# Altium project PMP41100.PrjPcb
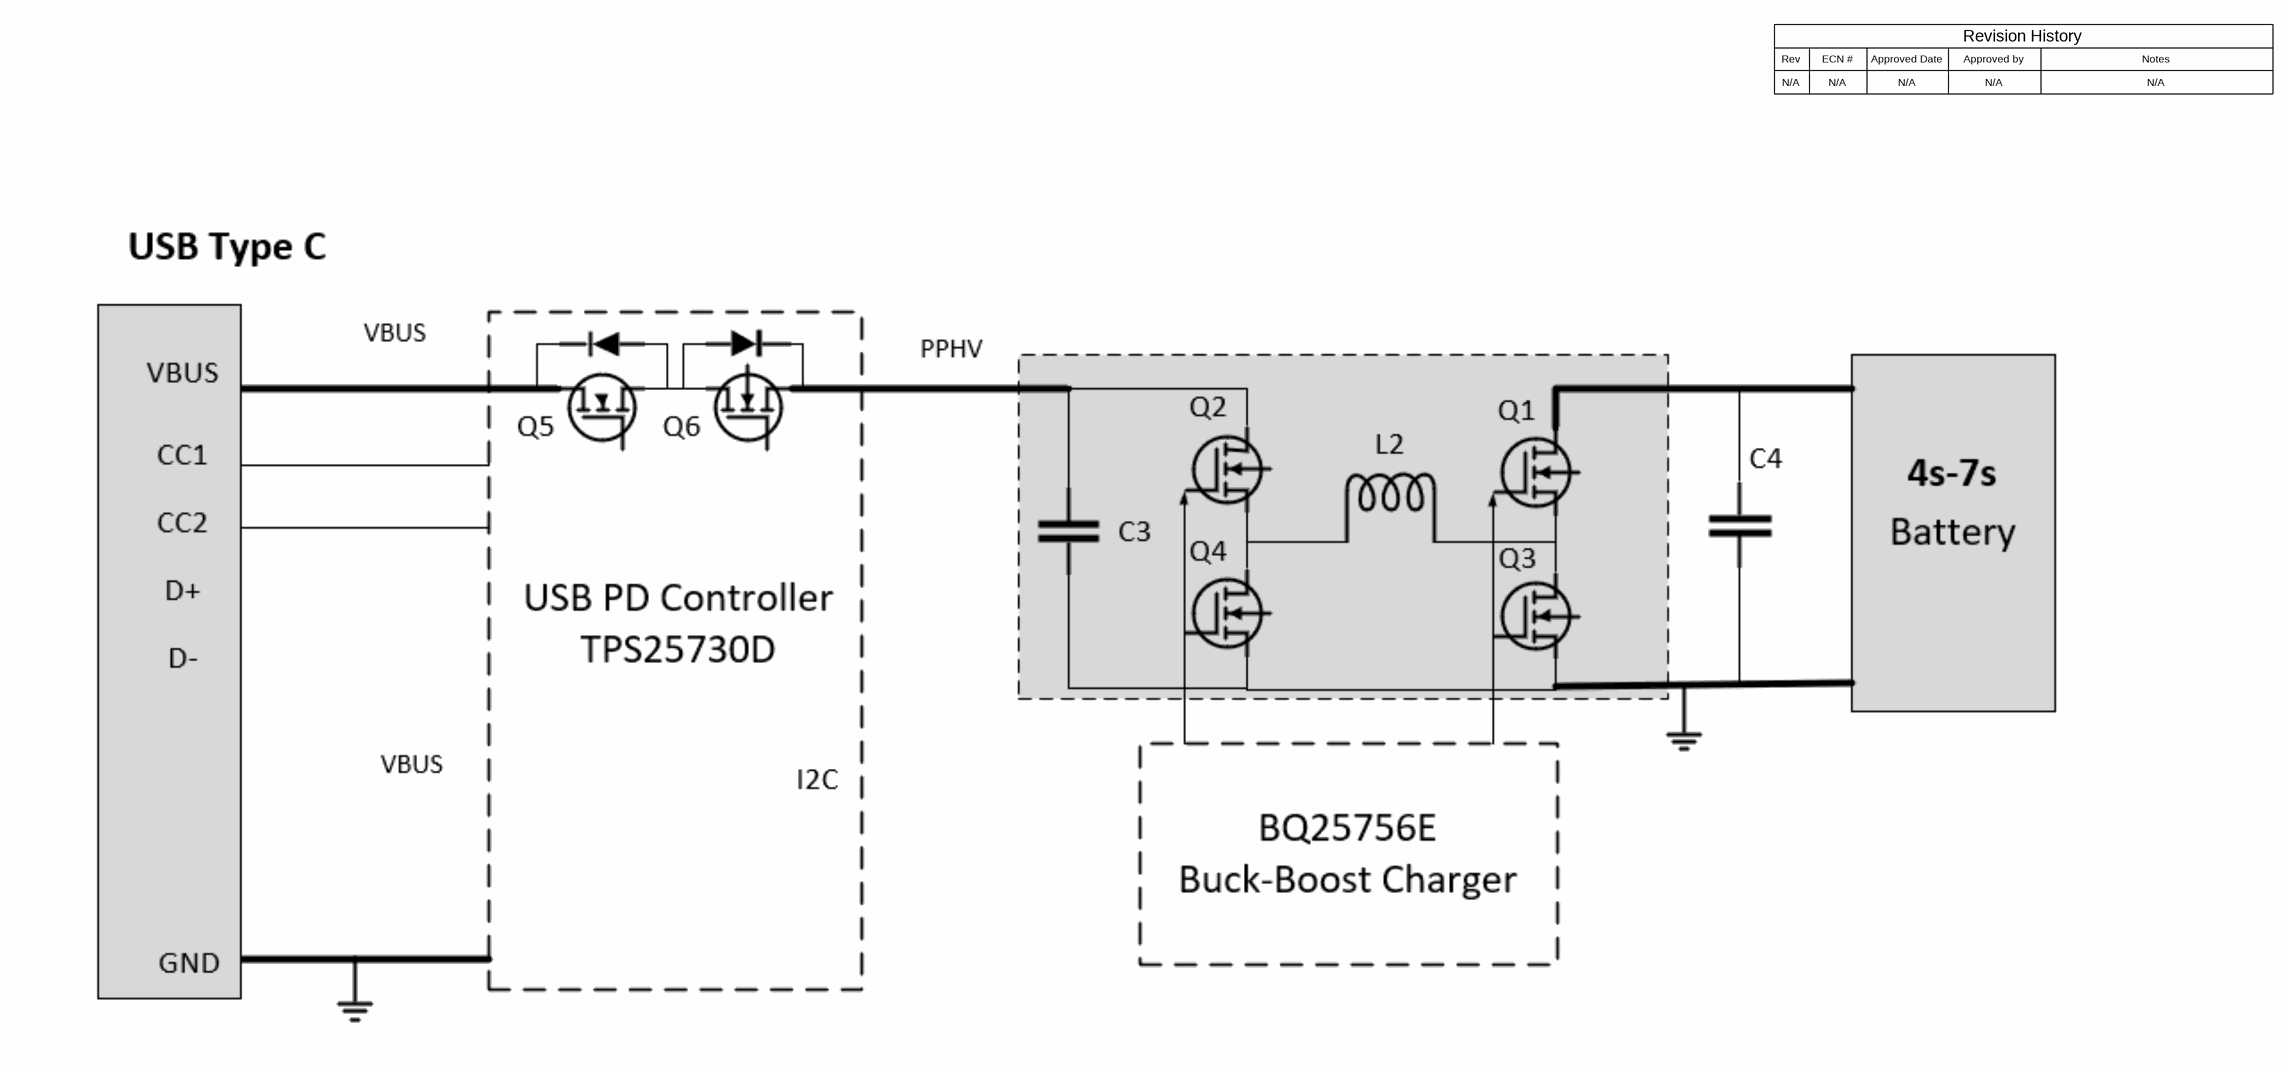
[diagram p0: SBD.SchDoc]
TechSupport: http://www.ti.com/support; SCH_Rev: E1; PRJ_Title: PMP41100; PRJ_Number: PMP41100; PRJ_Engineer: Max Wang; PRJ_Customer: Public Release; PCB_Rev: E1; PCB_Layout: Max Wang; CopyrightYear: 2018
4 sheets, 102 parts. Net scope: flat (ports and power ports of the same name join across sheets).
Board file: PMP41100.PcbDoc
Sheets:
  SBD.SchDoc
  PD Controller.SchDoc
  Charger BQ25756.SchDoc
  Hardware.SchDoc

## Sheet SBD.SchDoc
size A2; Date: Not shown in title block; ApprovedBy: Not shown in title block; CheckedBy: Not shown in title block; Author: Not shown in title block; CompanyName: Not shown in title block; Engineer: Not shown in title block; Organization: Not shown in title block; Address1: Not shown in title block; Address2: Not shown in title block; Address3: Not shown in title block; Address4: Not shown in title block; DocumentNumber: 1; Revision: Use project parameter SCH_Rev; SheetNumber: 1; SheetTotal: 4; PageSetup: Record=PageOptions¦CenterHorizontal=True¦CenterVertical=True¦PrintScale=1.00¦XCorrection=1.00¦YCorrection=1.00¦PrintKind=0¦BorderSize=5000000¦LeftOffset=0¦BottomOffset=0¦Orientation=2¦PaperLength=1000¦PaperWidth=1000¦Scale=100¦PaperSource=15¦PrintQuality=600¦MediaType=1¦DitherType=10¦PaperKind=Letter¦PrintScaleMode=1

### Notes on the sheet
- Revision History
- Rev
- N/A
- ECN #
- Approved Date
- Approved by
- Notes

## Sheet PD Controller.SchDoc
size A2; Date: Not shown in title block; ApprovedBy: Not shown in title block; CheckedBy: Not shown in title block; Author: Not shown in title block; CompanyName: Not shown in title block; Engineer: Not shown in title block; Organization: Not shown in title block; Address1: Not shown in title block; Address2: Not shown in title block; Address3: Not shown in title block; Address4: Not shown in title block; DocumentNumber: 1; Revision: Use project parameter SCH_Rev; SheetNumber: 2; SheetTotal: 4; PageSetup: Record=PageOptions¦CenterHorizontal=True¦CenterVertical=True¦PrintScale=1.00¦XCorrection=1.00¦YCorrection=1.00¦PrintKind=0¦BorderSize=5000000¦LeftOffset=0¦BottomOffset=0¦Orientation=2¦PaperLength=1000¦PaperWidth=1000¦Scale=100¦PaperSource=15¦PrintQuality=600¦MediaType=1¦DitherType=10¦PaperKind=Letter¦PrintScaleMode=1
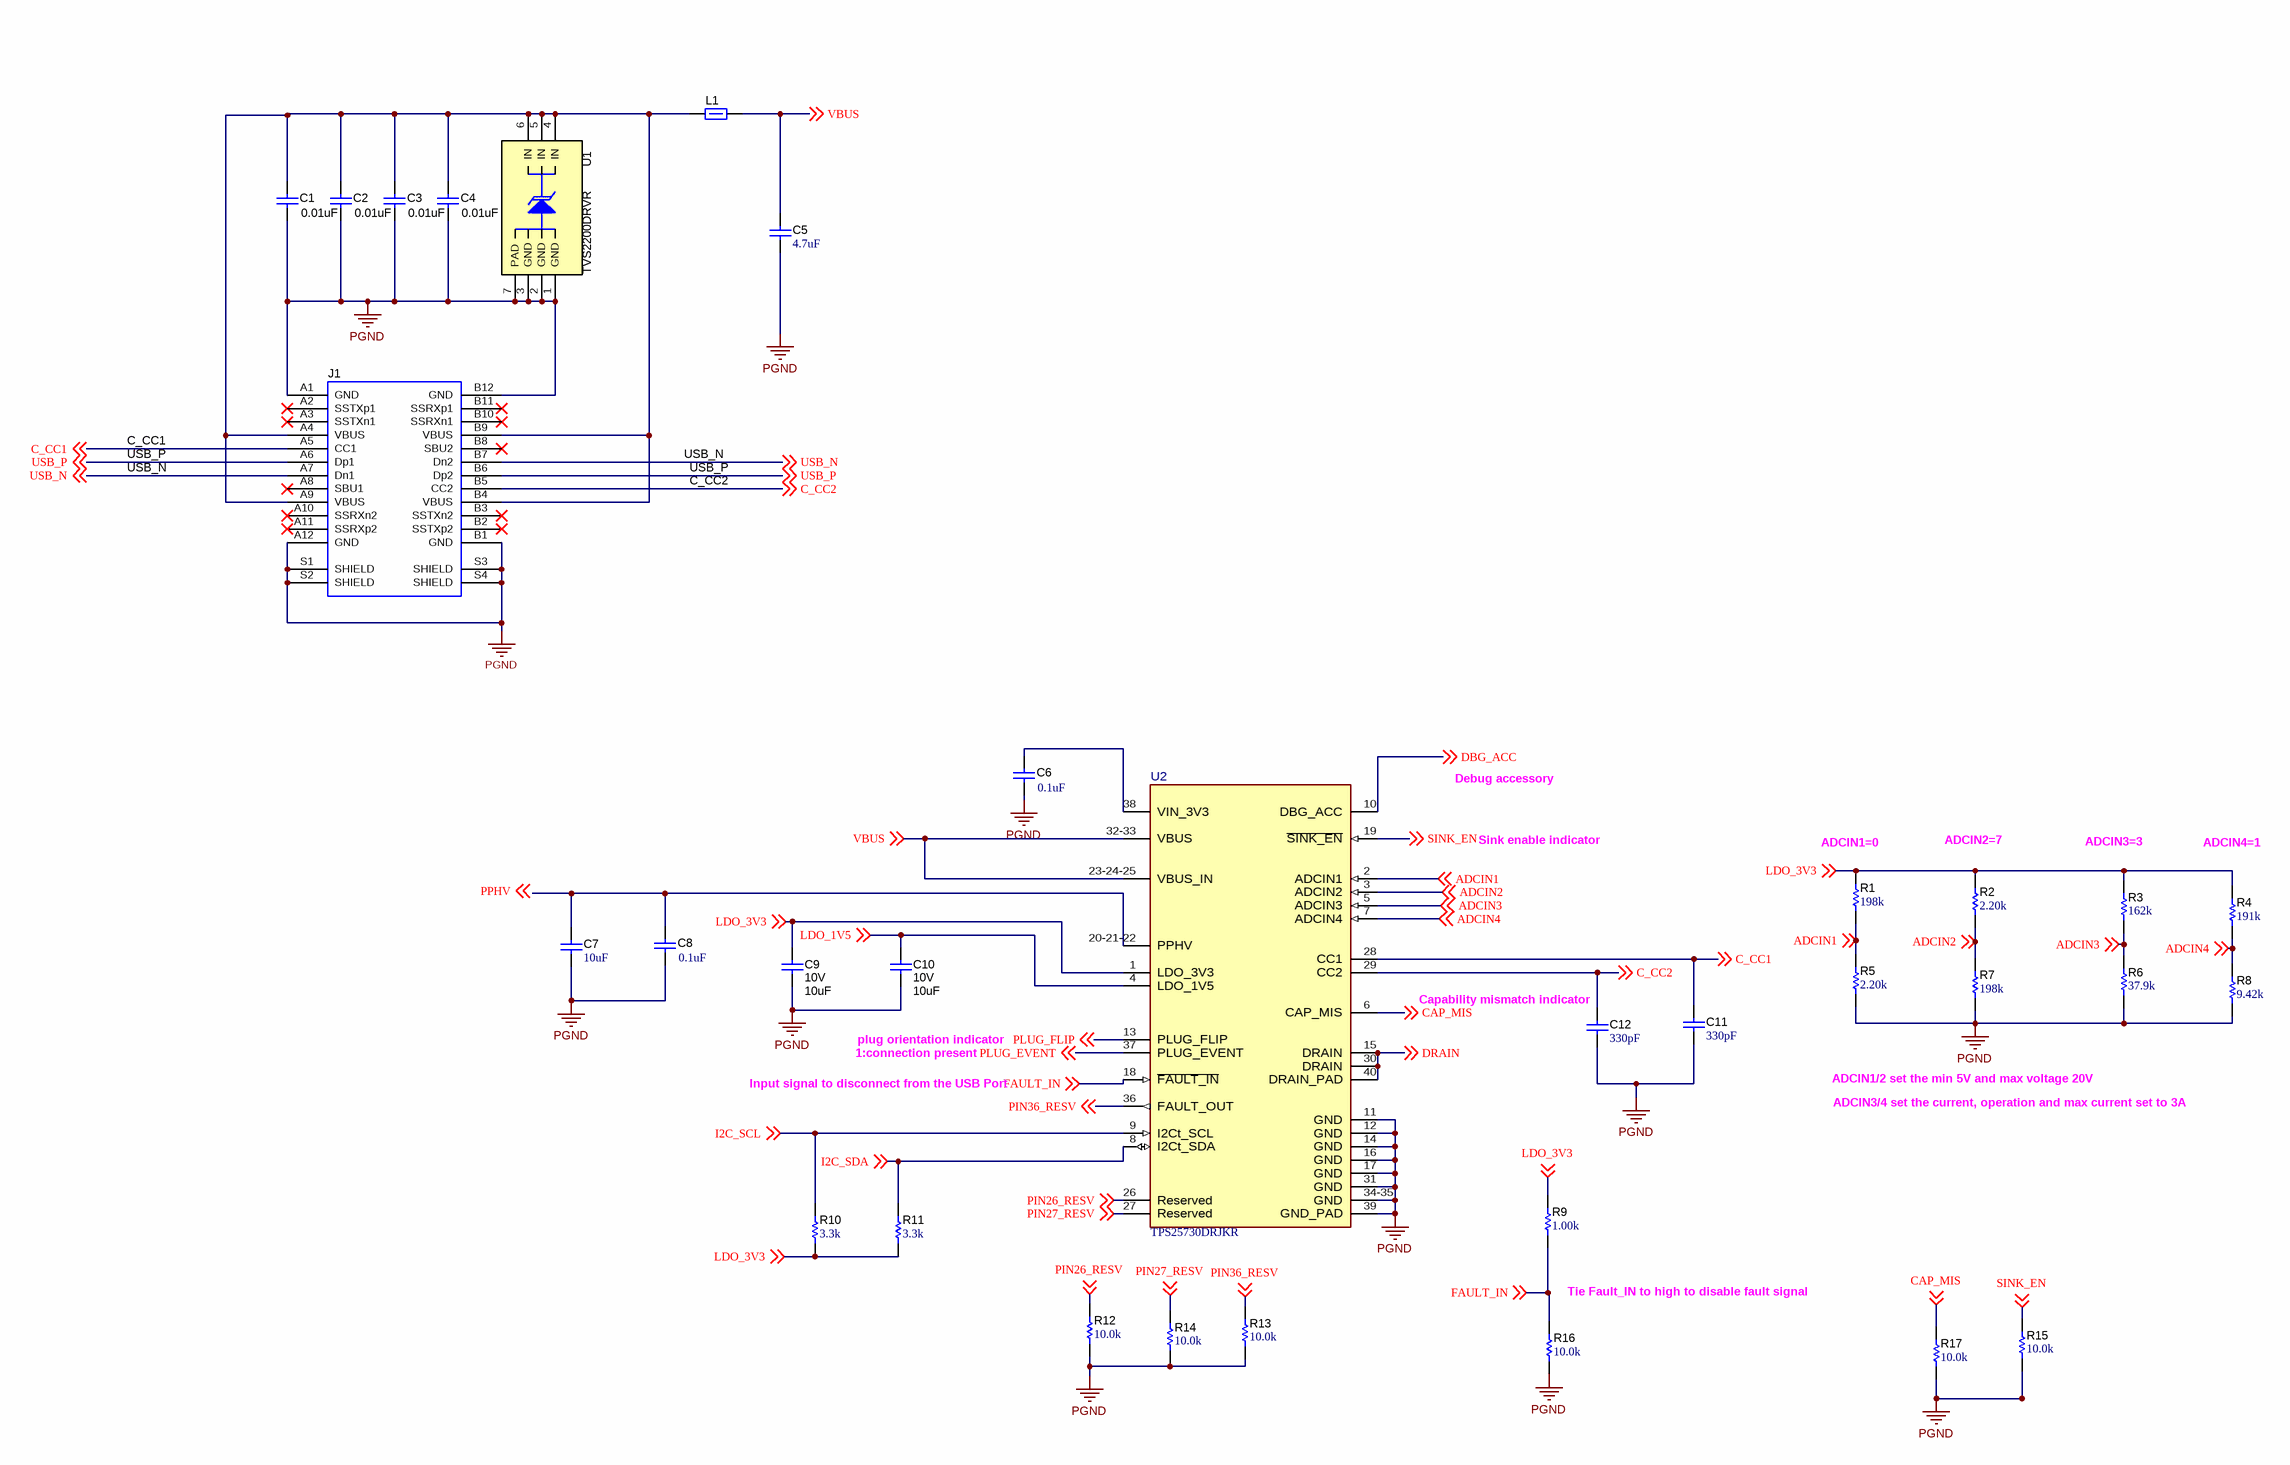
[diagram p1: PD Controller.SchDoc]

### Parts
C1  ValueDisplayed: 0.01uF  [0402]  (hidden comment: C0402C103J5RACTU)
C2  ValueDisplayed: 0.01uF  [0402]  (hidden comment: C0402C103J5RACTU)
C3  ValueDisplayed: 0.01uF  [0402]  (hidden comment: C0402C103J5RACTU)
C4  ValueDisplayed: 0.01uF  [0402]  (hidden comment: C0402C103J5RACTU)
C5  ValueDisplayed: 4.7uF  [0805_HV]  (hidden comment: GRM21BR61H475KE51L)
C6  ValueDisplayed: 0.1uF  [0603]  (hidden comment: GCM188R71H104KA57D)
C7  ValueDisplayed: 10uF  [1206_180]  (hidden comment: CL31B106KBHNNNE)
C8  ValueDisplayed: 0.1uF  [0603]  (hidden comment: GCM188R71H104KA57D)
C9  VDC_V: 10V  ValueDisplayed: 10uF  [0402_070]  (hidden comment: CL05A106MP5NUNC)
C10  VDC_V: 10V  ValueDisplayed: 10uF  [0402_070]  (hidden comment: CL05A106MP5NUNC)
C11  ValueDisplayed: 330pF  [0201_033]  (hidden comment: CGA1A2X7R1H331K030BA)
C12  ValueDisplayed: 330pF  [0201_033]  (hidden comment: CGA1A2X7R1H331K030BA)
J1  DX07S024JJ2R1300  [JAE_DX07S024JJ2R1300]  (value not drawn)
L1  FBMJ2125HM210NT  [0805_HV]  (value not drawn)
R1  ValueDisplayed: 198k  [0603]  (hidden comment: RT0603BRD07198KL)
R2  ValueDisplayed: 2.20k  [0603]  (hidden comment: RG1608P-222-B-T5)
R3  ValueDisplayed: 162k  [0603]  (hidden comment: RT0603BRD07162KL)
R4  ValueDisplayed: 191k  [0603]  (hidden comment: RT0603DRE07191KL)
R5  ValueDisplayed: 2.20k  [0603]  (hidden comment: RG1608P-222-B-T5)
R6  ValueDisplayed: 37.9k  [0603]  (hidden comment: RT0603DRE0737K9L)
R7  ValueDisplayed: 198k  [0603]  (hidden comment: RT0603BRD07198KL)
R8  ValueDisplayed: 9.42k  [0603]  (hidden comment: RT0603BRD079K42L)
R9  ValueDisplayed: 1.00k  [0603]  (hidden comment: RT0603BRD071KL)
R10  ValueDisplayed: 3.3k  [0402]  (hidden comment: CRCW04023K30JNED)
R11  ValueDisplayed: 3.3k  [0402]  (hidden comment: CRCW04023K30JNED)
R12  ValueDisplayed: 10.0k  [0402]  (hidden comment: ERJ-2RKF1002X)
R13  ValueDisplayed: 10.0k  [0402]  (hidden comment: ERJ-2RKF1002X)
R14  ValueDisplayed: 10.0k  [0402]  (hidden comment: ERJ-2RKF1002X)
R15  ValueDisplayed: 10.0k  [0402]  (hidden comment: ERJ-2RKF1002X)
R16  ValueDisplayed: 10.0k  [0402]  (hidden comment: ERJ-2RKF1002X)
R17  ValueDisplayed: 10.0k  [0402]  (hidden comment: ERJ-2RKF1002X)
U1  TVS2200DRVR  [DRV0006A]
U2  TPS25730DRJKR  [RJK0038B-MFG]

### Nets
PGND: C1.2 C2.2 C3.2 C4.2 C5.2 C6.2 C7.2 C8.2 C9.1 C10.1 C11.2 C12.2 J1.A1(GND) J1.A12(GND) J1.B1(GND) J1.B12(GND) J1.S1(SHIELD) J1.S2(SHIELD) J1.S3(SHIELD) J1.S4(SHIELD) R5.1 R6.1 R7.1 R8.1 R12.1 R13.1 R14.1 R15.1 R16.1 R17.1 U1.1(GND) U1.2(GND) U1.3(GND) U1.7(PAD) U2.11(GND) U2.12(GND) U2.14(GND) U2.16(GND) U2.17(GND) U2.31(GND) U2.34-35(GND) U2.39(GND_PAD)
ADCIN1: R1.1 R5.2 U2.2(ADCIN1) ; off-sheet ADCIN1
ADCIN2: R2.1 R7.2 U2.3(ADCIN2) ; off-sheet ADCIN2
ADCIN3: R3.1 R6.2 U2.5(ADCIN3) ; off-sheet ADCIN3
ADCIN4: R4.1 R8.2 U2.7(ADCIN4) ; off-sheet ADCIN4
C_CC1: C11.1 J1.A5(CC1) U2.28(CC1) ; off-sheet C_CC1
C_CC2: C12.1 J1.B5(CC2) U2.29(CC2) ; off-sheet C_CC2
CAP_MIS: R17.2 U2.6(CAP_MIS) ; off-sheet CAP_MIS
DBG_ACC: U2.10(DBG_ACC) ; off-sheet DBG_ACC
DRAIN: U2.15(DRAIN) U2.30(DRAIN) U2.40(DRAIN_PAD) ; off-sheet DRAIN
FAULT_IN: R9.1 R16.2 U2.18(~{FAULT_IN}) ; off-sheet FAULT_IN
I2C_SCL: R10.2 U2.9(I2Ct_SCL) ; off-sheet I2C_SCL
I2C_SDA: R11.2 U2.8(I2Ct_SDA) ; off-sheet I2C_SDA
LDO_1V5: C10.2 U2.4(LDO_1V5) ; off-sheet LDO_1V5
LDO_3V3: C9.2 R1.2 R2.2 R3.2 R4.2 R9.2 R10.1 R11.1 U2.1(LDO_3V3) ; off-sheet LDO_3V3
PIN26_RESV: R12.2 U2.26(Reserved) ; off-sheet PIN26_RESV
PIN27_RESV: R14.2 U2.27(Reserved) ; off-sheet PIN27_RESV
PIN36_RESV: R13.2 U2.36(FAULT_OUT) ; off-sheet PIN36_RESV
PLUG_EVENT: U2.37(PLUG_EVENT) ; off-sheet PLUG_EVENT
PLUG_FLIP: U2.13(PLUG_FLIP) ; off-sheet PLUG_FLIP
SINK_EN: R15.2 U2.19(~{SINK_EN}) ; off-sheet SINK_EN
USB_N: J1.A7(Dn1) J1.B7(Dn2) ; off-sheet USB_N
USB_P: J1.A6(Dp1) J1.B6(Dp2) ; off-sheet USB_P
VBUS: C5.1 L1.2 U2.23-24-25(VBUS_IN) U2.32-33(VBUS) ; off-sheet VBUS
NetC1_1: C1.1 C2.1 C3.1 C4.1 J1.A4(VBUS) J1.A9(VBUS) J1.B4(VBUS) J1.B9(VBUS) L1.1 U1.4(IN) U1.5(IN) U1.6(IN)
NetC6_1: C6.1 U2.38(VIN_3V3)
NetC7_1: C7.1 C8.1 U2.20-21-22(PPHV)

Not connected (* = marked no-connect by the designer): J1 A2(SSTXp1)* A3(SSTXn1)* A8(SBU1)* A10(SSRXn2)* A11(SSRXp2)* B2(SSTXp2)* B3(SSTXn2)* B8(SBU2)* B10(SSRXn1)* B11(SSRXp1)*

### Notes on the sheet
- Debug accessory
- Sink enable indicator
- (near R1) ADCIN1=0
- (near R2) ADCIN2=7
- (near R3) ADCIN3=3
- (near R4) ADCIN4=1
- (near C12) Capability mismatch indicator
- Input signal to disconnect from the USB Port
- 1:connection present
- plug orientation indicator
- ADCIN1/2 set the min 5V and max voltage 20V
- ADCIN3/4 set the current, operation and max current set to 3A
- Tie Fault_IN to high to disable fault signal
- Labels drawn without touching a wire or pin: PPHV

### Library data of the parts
C1-C4 = CMP-0006236-2: CAP, CERM, 0.01 uF, 50 V, +/- 5%, X7R, 0402; Manufacturer: Kemet; TaMin_C: -55°C; Polarized: N; SizeAreaWB_mm2: 3; Value1: Unknown; U/M: EA; Value: 0.01uF; TaMax_C: 125°C; SizeZ_mm: 0.6; SizeX_mm: 1; SizeY_mm: 0.5; Value2: 50V; CompType: Capacitor; Cap_F: 10nF; AEC Category: Q200
C5 = CMP-0008309-2: CAP, CERM, 4.7 uF, 50 V, +/- 10%, X5R, 0805; Manufacturer: MuRata; TaMin_C: -55°C; Polarized: N; SizeAreaWB_mm2: 6.75; Value1: Unknown; U/M: EA; Value: 4.7uF; TaMax_C: 85°C; SizeZ_mm: 1.45; SizeX_mm: 2; SizeY_mm: 1.25; Cap_Case: 0805; Value2: 50V; SizeArea_mm2: 2.5; Cap_F: 4.7µF; AEC Category: Q200
C6 C8 = CMP-0007144-4: CAP, CERM, 0.1 uF, 50 V, +/- 10%, X7R, 0603; Manufacturer: MuRata; TaMin_C: -55°C; Polarized: N; SizeAreaWB_mm2: 4.68; Value1: 0.02 ohm; U/M: EA; Value: 0.1uF; TaMax_C: 125°C; SizeZ_mm: 1; SizeX_mm: 1.6; SizeY_mm: 0.8; Value2: 50V; SizeArea_mm2: 1.28; Cap_F: 100nF; AEC Category: Q200; ESR_ohm: 20m; IRMS_A: 1.84A
C7 = CMP-0008802-2: CAP, CERM, 10 uF, 50 V, +/- 10%, X7R, 1206; Manufacturer: Samsung; TaMin_C: -55°C; Polarized: N; SizeAreaWB_mm2: 10.92; Value1: Unknown; U/M: EA; Value: 10uF; TaMax_C: 125°C; SizeZ_mm: 1.8; SizeX_mm: 3.2; SizeY_mm: 1.6; Cap_Case: 1206; Value2: 50V; SizeArea_mm2: 5.12; Cap_F: 10µF; AEC Category: Q200
C9 C10 = CMP-0006339-4: CAP, CERM, 10 uF, 10 V, +/- 20%, X5R, 0402; Manufacturer: Samsung Electro-Mechanics; TaMin_C: -55°C; Polarized: N; SizeAreaWB_mm2: 3; Value1: Unknown; U/M: EA; Value: 10uF; TaMax_C: 85°C; SizeZ_mm: 0.6; SizeX_mm: 1; SizeY_mm: 0.5; Cap_Case: 0402; Cap_F: 10µF; AEC Category: Q200
C11 C12 = CMP-0009653-3: CAP, CERM, 330 pF, 50 V, +/- 10%, X7R, AEC-Q200 Grade 1, 0201; Manufacturer: TDK; TaMin_C: -55°C; ESR_ohm: 8.053; Polarized: N; SizeAreaWB_mm2: 2.08; Value1: 8.05302 ohm; U/M: EA; Value: 330pF; TaMax_C: 125°C; SizeZ_mm: 0.33; SizeX_mm: 0.6; SizeY_mm: 0.3; Value2: 50V; SizeArea_mm2: 0.18; AEC Qualified: Y; IRMS_A: 210.618mA; AEC Grade: 1; AEC Category: Q200
J1 = CMP-0085712-2: Receptacle, USB 3.1 Type C, R/A, Gold, SMT; Manufacturer: JAE Electronics; Current_A: 1.25A; Gender: Female; Voltage_V: 20V; Pitch_mm: 0.5; Row_Count: 2
L1 = CMP-0003375-1: Ferrite Bead, 21 ohm @ 100 MHz, 6 A, 0805; Manufacturer: Taiyo Yuden; ZTyp@100MHz_Ohm: 21; SizeAreaWB_mm2: 6.75; DCR_ohm: 4m; Value1: 0.004 ohm; Value: 21 ohm; Imax_A: 6A; SizeZ_mm: 1.45; SizeX_mm: 2; SizeY_mm: 1.25; SizeArea_mm2: 2.5
R1 R7 = CMP-0023852-1: RES, 198 k, 0.1%, 0.1 W, 0603; Manufacturer: Yageo America; Power_W: 100mW; TempCo: 25 ppm/C; U/M: EA; Value: 198k; EIA_Code: E192; SizeX_mm: 1.6; SizeY_mm: 0.8; SizeZ_mm: 1; Value2: 0.1W; SizeArea_mm2: 1.28; VDC_V: 75V; AEC Category: Q200
R2 R5 = CMP-0023473-2: RES, 2.20 k, 0.1%, 0.1 W, 0603; Manufacturer: Susumu Co Ltd; Power_W: 100mW; TempCo: 25 ppm/C; Value_Code: 2k20; U/M: EA; Value: 2.20k; Res_ohm: 2.2k; SizeX_mm: 1.6; SizeY_mm: 0.8; SizeZ_mm: 1; Value2: 0.1W; SizeArea_mm2: 1.28; VDC_V: 75V; AEC Category: Q200
R3 = CMP-0023788-2: RES, 162 k, 0.1%, 0.1 W, 0603; Manufacturer: Yageo America; Power_W: 100mW; TempCo: 25 ppm/C; U/M: EA; Value: 162k; EIA_Code: E192; SizeX_mm: 1.6; SizeY_mm: 0.8; SizeZ_mm: 1; Value2: 0.1W; SizeArea_mm2: 1.28; VDC_V: 75V; AEC Category: Q200
R4 = CMP-0024779-3: RES, 191 k, 0.5%, 0.1 W, 0603; Manufacturer: Yageo America; Power_W: 100mW; TempCo: 50 ppm/C; U/M: EA; Value: 191k; EIA_Code: E192; SizeX_mm: 1.6; SizeY_mm: 0.8; SizeZ_mm: 1; Value2: 0.1W; SizeArea_mm2: 1.28; VDC_V: 75V; AEC Category: Q200
R6 = CMP-0025190-2: RES, 37.9 k, 0.5%, 0.1 W, 0603; Manufacturer: Yageo America; Power_W: 100mW; TempCo: 50 ppm/C; Value_Code: 37k9; U/M: EA; Value: 37.9k; EIA_Code: E192; SizeX_mm: 1.6; SizeY_mm: 0.8; SizeZ_mm: 1; Value2: 0.1W; SizeArea_mm2: 1.28; VDC_V: 75V; AEC Category: Q200
R8 = CMP-0024554-2: RES, 9.42 k, 0.1%, 0.1 W, 0603; Manufacturer: Yageo America; Power_W: 100mW; TempCo: 25 ppm/C; Value_Code: 9k42; U/M: EA; Value: 9.42k; EIA_Code: E192; SizeX_mm: 1.6; SizeY_mm: 0.8; SizeZ_mm: 1; Value2: 0.1W; SizeArea_mm2: 1.28; VDC_V: 75V; AEC Category: Q200
R9 = CMP-0023919-1: RES, 1.00 k, 0.1%, 0.1 W, 0603; Manufacturer: Yageo America; Power_W: 100mW; TempCo: 25 ppm/C; Value_Code: 1k00; U/M: EA; Value: 1.00k; EIA_Code: E192; Res_ohm: 1k; SizeX_mm: 1.6; SizeY_mm: 0.8; SizeZ_mm: 1; Value2: 0.1W; SizeArea_mm2: 1.28; VDC_V: 75V; AEC Category: Q200
R10 R11 = CMP-0026918-5: RES, 3.3 k, 5%, 0.063 W, AEC-Q200 Grade 0, 0402; Manufacturer: Vishay-Dale; Value: 3.3k; Value_Code: 3k30; Power_W: 63mW; Value2: 0.063W; VDC_V: 50V; TempCo: 200 ppm/C; SizeArea_mm2: 0.5; SizeX_mm: 1; SizeZ_mm: 0.6; EIA_Code: E24; AEC Category: Q200; AEC Qualified: Y; AEC Grade: 0
R12-R17 = CMP-0026658-1: RES, 10.0 k, 1%, 0.1 W, 0402; Manufacturer: Panasonic; Power_W: 100mW; TempCo: 100 ppm/C; Value_Code: 10k0; U/M: EA; Value: 10.0k; EIA_Code: E96; Res_ohm: 10k; SizeX_mm: 1; SizeY_mm: 0.5; SizeZ_mm: 0.6; Value2: 0.1W; VDC_V: 50V; AEC Category: Q200
U1 = CMP-0077834-1: 22-V Precision Surge Protection Clamp, DRV0006A (WSON-6); Alternate Manufacturer: Texas Instruments; SizeAreaWB_mm2: 9.0; SizeZ_mm: 0.8; SizeX_mm: 2.0; SizeArea_mm2: 4.0; CompType: IC; AEC Qualified: N; AEC Category: Q200
U2 = CMP-0095900-3: USB Type-C and USB PD Controller with Integrated Power Switches Optimized for Power Applications; Manufacturer: Texas Instruments; Number Of Ports: 1; Standoff Height: 0mm; Interface: I2C,USB; SizeZ_mm: 0.8mm; AEC Category: Q200; CompType: IC

## Sheet Charger BQ25756.SchDoc
size A2; Date: Not shown in title block; ApprovedBy: Not shown in title block; CheckedBy: Not shown in title block; Author: Not shown in title block; CompanyName: Not shown in title block; Engineer: Not shown in title block; Organization: Not shown in title block; Address1: Not shown in title block; Address2: Not shown in title block; Address3: Not shown in title block; Address4: Not shown in title block; DocumentNumber: 1; Revision: Use project parameter SCH_Rev; SheetNumber: 3; SheetTotal: 4; PageSetup: Record=PageOptions¦CenterHorizontal=True¦CenterVertical=True¦PrintScale=0.69¦XCorrection=1.00¦YCorrection=1.00¦PrintKind=0¦BorderSize=5000000¦LeftOffset=0¦BottomOffset=0¦Orientation=2¦PaperLength=1000¦PaperWidth=1000¦Scale=100¦PaperSource=15¦PrintQuality=600¦MediaType=1¦DitherType=10¦PaperKind=Letter¦PrintScaleMode=1
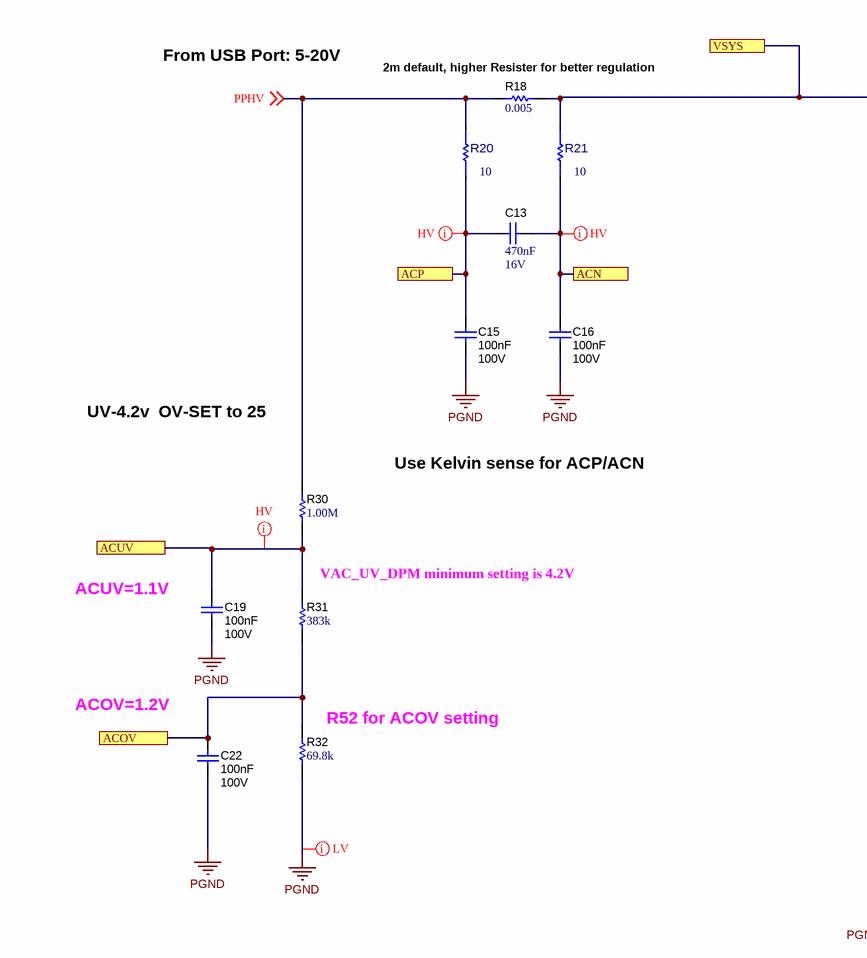
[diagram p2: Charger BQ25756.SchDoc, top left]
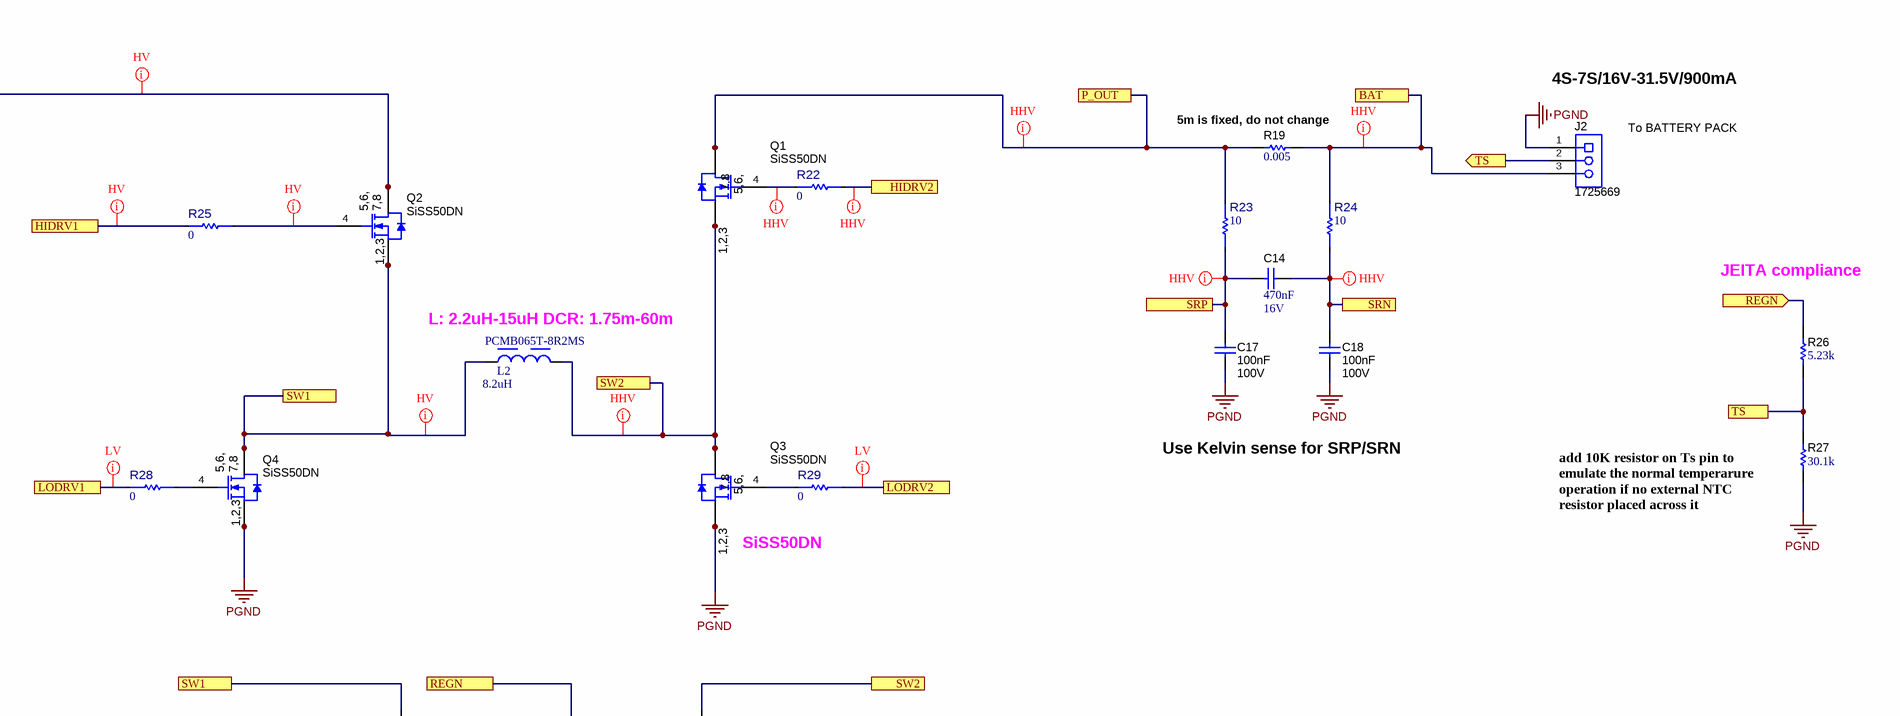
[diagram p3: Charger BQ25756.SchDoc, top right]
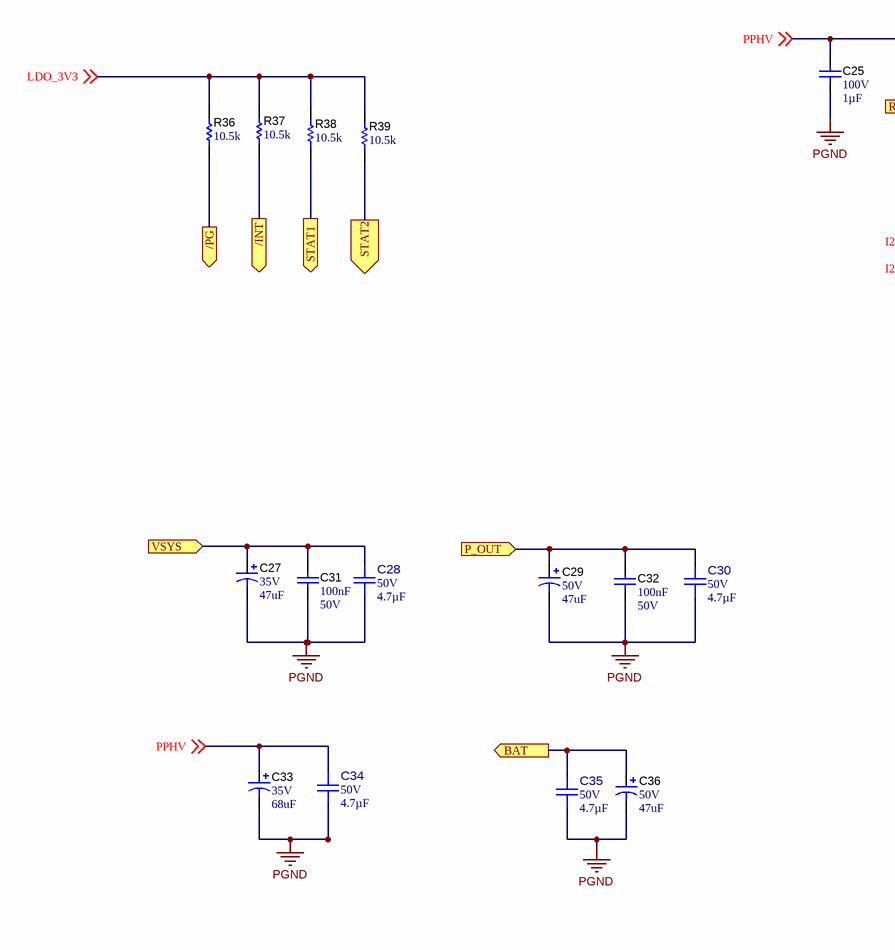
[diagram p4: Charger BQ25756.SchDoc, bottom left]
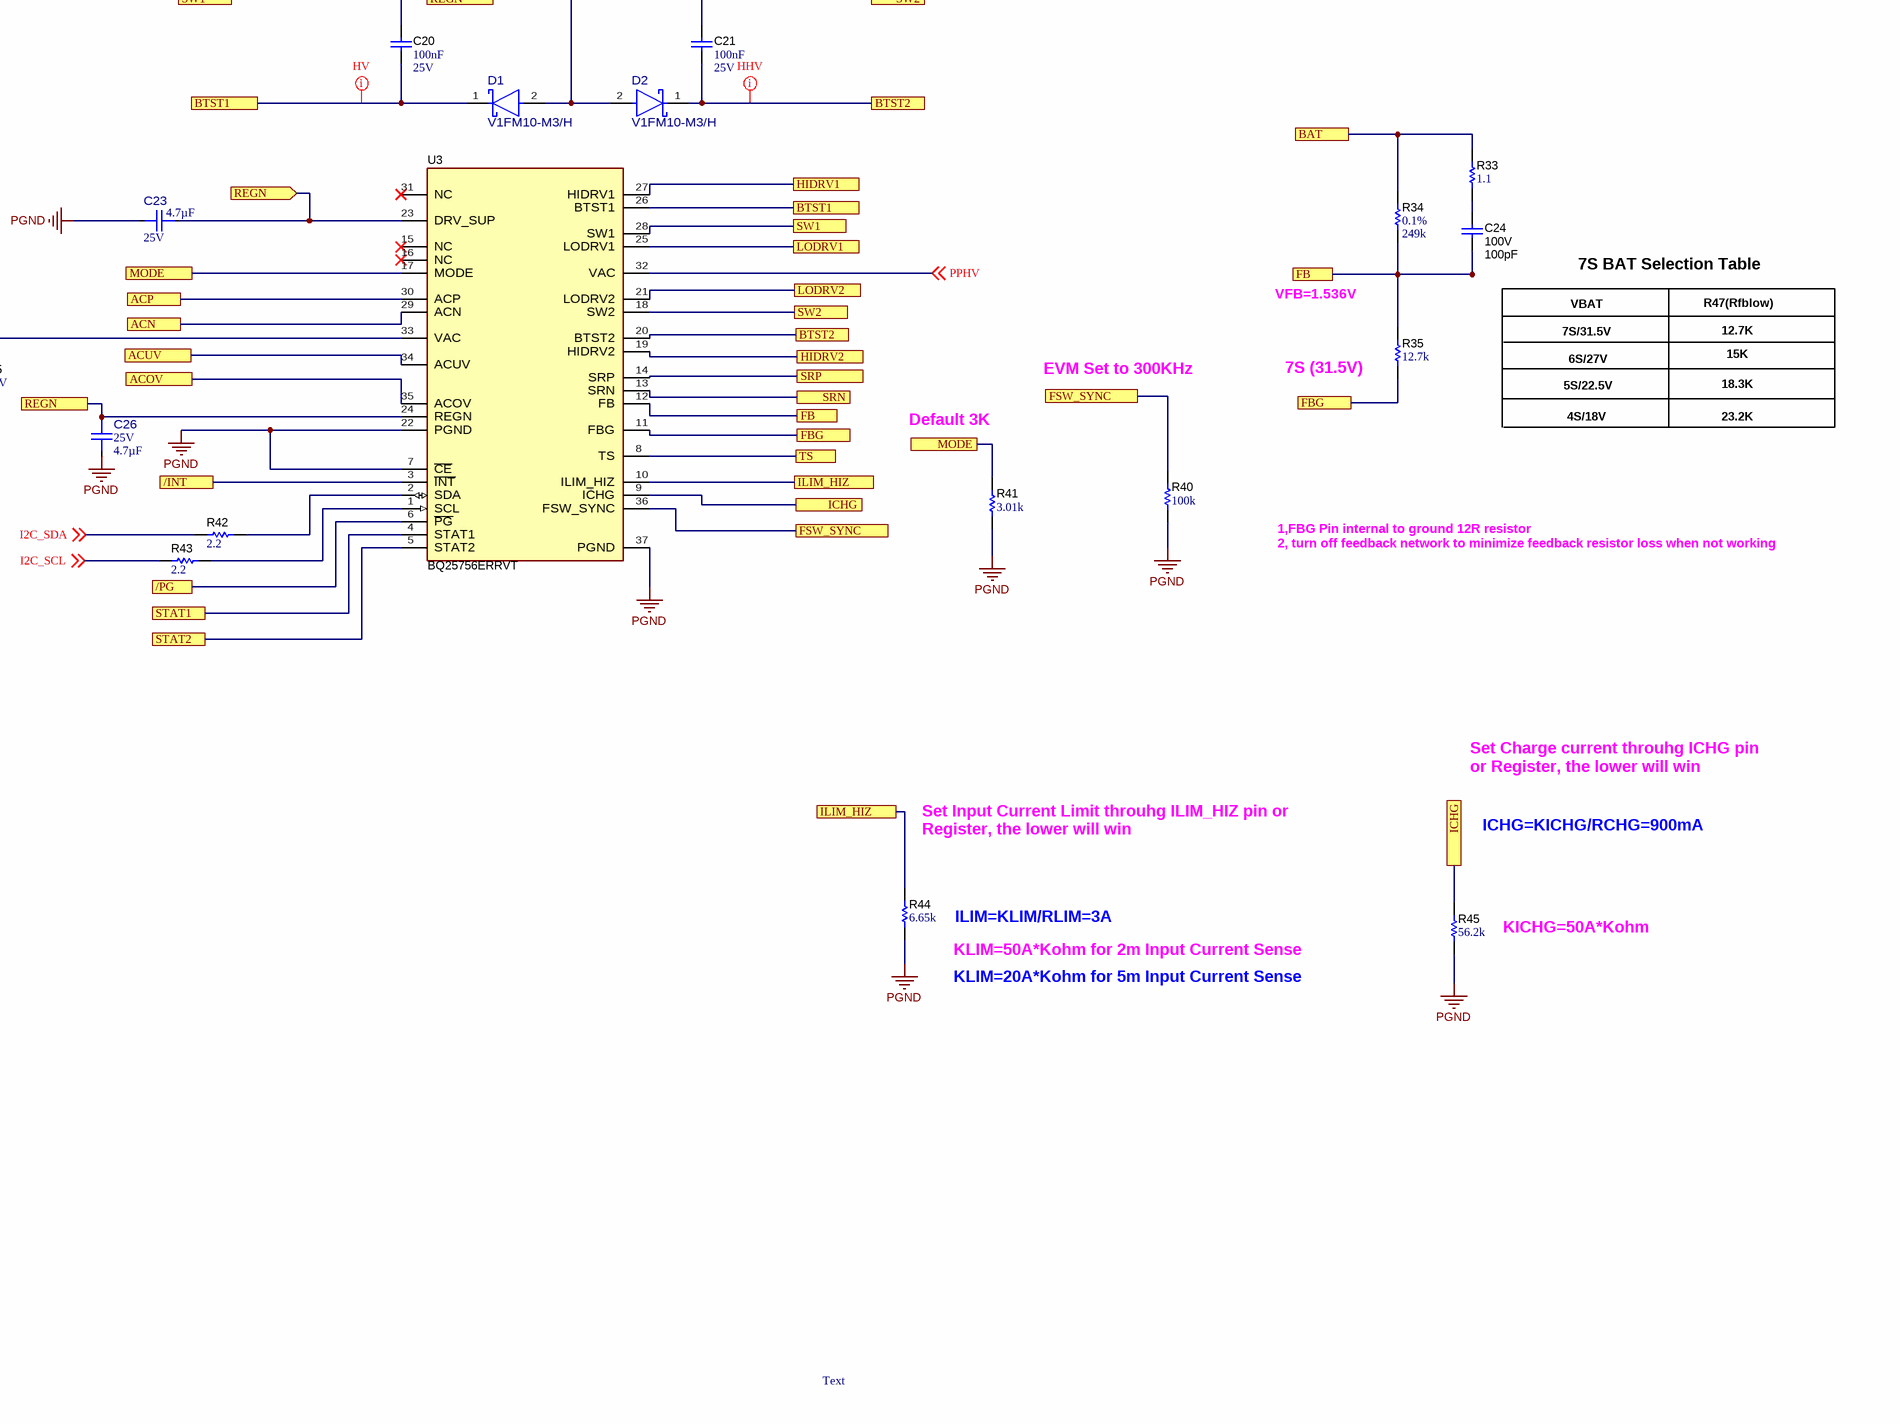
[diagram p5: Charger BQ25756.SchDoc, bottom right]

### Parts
C13  Cap_F: 470nF  VDC_V: 16V  [0603]  (hidden comment: C0603C474K4RACTU)
C14  Cap_F: 470nF  VDC_V: 16V  [0603]  (hidden comment: C0603C474K4RACTU)
C15  Cap_F: 100nF  VDC_V: 100V  [0603_HV]  (hidden comment: HMK107B7104KAHT)
C16  Cap_F: 100nF  VDC_V: 100V  [0603_HV]  (hidden comment: HMK107B7104KAHT)
C17  Cap_F: 100nF  VDC_V: 100V  [0603_HV]  (hidden comment: HMK107B7104KAHT)
C18  Cap_F: 100nF  VDC_V: 100V  [0603_HV]  (hidden comment: HMK107B7104KAHT)
C19  Cap_F: 100nF  VDC_V: 100V  [0603_HV]  (hidden comment: HMK107B7104KAHT)
C20  Cap_F: 100nF  VDC_V: 25V  [0603_HV]  (hidden comment: 06033C104KAT2A)
C21  Cap_F: 100nF  VDC_V: 25V  [0603_HV]  (hidden comment: 06033C104KAT2A)
C22  Cap_F: 100nF  VDC_V: 100V  [0603_HV]  (hidden comment: HMK107B7104KAHT)
C23  VDC_V: 25V  Cap_F: 4.7µF  [FP-CGA4J1X7R1E475K125AE_0805-MFG]  (hidden comment: CGA4J1X7R1E475K125AE)
C24  VDC_V: 100V  ValueDisplayed: 100pF  [0603_HV]  (hidden comment: GCM1885C2A101JA16D)
C25  VDC_V: 100V  Cap_F: 1µF  [0805_150]  (hidden comment: 08051C105K4Z2A)
C26  VDC_V: 25V  Cap_F: 4.7µF  [FP-CGA4J1X7R1E475K125AE_0805-MFG]  (hidden comment: CGA4J1X7R1E475K125AE)
C27  VDC_V: 35V  ValueDisplayed: 47uF  [SM_RADIAL_6.3AMM]  (hidden comment: EEHZA1V470P)
C28  VDC_V: 50V  Cap_F: 4.7µF  [FP-C2012X7R1H475K125AC_0805-MFG]  (hidden comment: C2012X7R1H475K125AC)
C29  VDC_V: 50V  ValueDisplayed: 47uF  [CM_630x580]  (hidden comment: UCM1H470MCL1GS)
C30  VDC_V: 50V  Cap_F: 4.7µF  [FP-C2012X7R1H475K125AC_0805-MFG]  (hidden comment: C2012X7R1H475K125AC)
C31  Cap_F: 100nF  VDC_V: 50V  [0603]  (hidden comment: C0603C104K5RACTU)
C32  Cap_F: 100nF  VDC_V: 50V  [0603]  (hidden comment: C0603C104K5RACTU)
C33  VDC_V: 35V  ValueDisplayed: 68uF  [ZC_D8]  (hidden comment: EEH-ZC1V680XP)
C34  VDC_V: 50V  Cap_F: 4.7µF  [FP-C2012X7R1H475K125AC_0805-MFG]  (hidden comment: C2012X7R1H475K125AC)
C35  VDC_V: 50V  Cap_F: 4.7µF  [FP-C2012X7R1H475K125AC_0805-MFG]  (hidden comment: C2012X7R1H475K125AC)
C36  VDC_V: 50V  ValueDisplayed: 47uF  [CM_630x580]  (hidden comment: UCM1H470MCL1GS)
D1  V1FM10-M3/H  [FP-V1FM10-M3-H_DO-219AB-MFG]
D2  V1FM10-M3/H  [FP-V1FM10-M3-H_DO-219AB-MFG]
J2  1725669  [Phoenix_1725669]
L2  PCMB065T-8R2MS  Inductance: 8.2uH  [WE-LHMI_7050]
Q1  SiSS50DN  [PowerPAK_1212-8]
Q2  SiSS50DN  [PowerPAK_1212-8]
Q3  SiSS50DN  [PowerPAK_1212-8]
Q4  SiSS50DN  [PowerPAK_1212-8]
R18  ValueDisplayed: 0.005  [WSL0805]  (hidden comment: WSLP08055L000FEA)
R19  ValueDisplayed: 0.005  [WSL0805]  (hidden comment: WSLP08055L000FEA)
R20  value 10  [FP-CRCW060310R0FKEB_0603-MFG]  (hidden comment: CRCW060310R0FKEB)
R21  value 10  [FP-CRCW060310R0FKEB_0603-MFG]  (hidden comment: CRCW060310R0FKEB)
R22  value 0  [FP-CRCW06031R50FKEAHP_0603-MFG]  (hidden comment: CRCW06030000Z0EA)
R23  value 10  [FP-CRCW060310R0FKEB_0603-MFG]  (hidden comment: CRCW060310R0FKEB)
R24  value 10  [FP-CRCW060310R0FKEB_0603-MFG]  (hidden comment: CRCW060310R0FKEB)
R25  value 0  [FP-CRCW06031R50FKEAHP_0603-MFG]  (hidden comment: CRCW06030000Z0EA)
R26  ValueDisplayed: 5.23k  [0603]  (hidden comment: RC0603FR-075K23L)
R27  ValueDisplayed: 30.1k  [0603]  (hidden comment: RC0603FR-0730K1L)
R28  value 0  [FP-CRCW06031R50FKEAHP_0603-MFG]  (hidden comment: CRCW06030000Z0EA)
R29  value 0  [FP-CRCW06031R50FKEAHP_0603-MFG]  (hidden comment: CRCW06030000Z0EA)
R30  ValueDisplayed: 1.00M  [0805_HV]  (hidden comment: CRCW08051M00FKEAC)
R31  ValueDisplayed: 383k  [0603]  (hidden comment: RT0603DRE07383KL)
R32  ValueDisplayed: 69.8k  [0603]  (hidden comment: RT0603DRE0769K8L)
R33  ValueDisplayed: 1.1  [0603]  (hidden comment: CRCW06031R10JNEA)
R34  Value1: 0.1%  ValueDisplayed: 249k  [0805_HV]  (hidden comment: ERJ-PB6B2493V)
R35  ValueDisplayed: 12.7k  [0603]  (hidden comment: RT0603BRD0712K7L)
R36  ValueDisplayed: 10.5k  [0402]  (hidden comment: RC0402FR-0710K5L)
R37  ValueDisplayed: 10.5k  [0402]  (hidden comment: RC0402FR-0710K5L)
R38  ValueDisplayed: 10.5k  [0402]  (hidden comment: RC0402FR-0710K5L)
R39  ValueDisplayed: 10.5k  [0402]  (hidden comment: RC0402FR-0710K5L)
R40  ValueDisplayed: 100k  [0603]  (hidden comment: RC0603FR-07100KL)
R41  ValueDisplayed: 3.01k  [0603]  (hidden comment: CRCW06033K01FKEA)
R42  ValueDisplayed: 2.2  [0402]  (hidden comment: CRCW04022R20JNED)
R43  ValueDisplayed: 2.2  [0402]  (hidden comment: CRCW04022R20JNED)
R44  ValueDisplayed: 6.65k  [0603]  (hidden comment: RT0603BRD076K65L)
R45  ValueDisplayed: 56.2k  [0603]  (hidden comment: RG1608P-5622-B-T5)
U3  PartNumber: BQ25756ERRVT  [RRV0036A-MFG]  (hidden comment: BQ25756RRVT)

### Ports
/INT, /INT (out), /PG, /PG (out), ACN, ACOV, ACP, ACUV, BAT, BAT (out), BTST1, BTST2, FB, FBG, FSW_SYNC, HIDRV1, HIDRV2, ICHG, ILIM_HIZ, LODRV1, LODRV2, MODE, P_OUT, P_OUT (in), REGN, REGN (in), SRN, SRP, STAT1, STAT1 (out), STAT2, STAT2 (out), SW1, SW2, TS, TS (out), VSYS, VSYS (in)

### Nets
PGND: C15.2 C16.2 C17.2 C18.2 C19.2 C22.2 C23.2 C25.2 C26.2 C27.2(-) C28.1 C29.2(-) C30.1 C31.2 C32.2 C33.2(-) C34.2 C35.1 C36.2(-) J2.1 Q3.1(S) Q3.2(S) Q3.3(S) Q4.1(S) Q4.2(S) Q4.3(S) R27.1 R32.1 R40.1 R41.1 R44.1 R45.1 U3.7(~{CE}) U3.22(PGND) U3.37(PGND)
/INT: R37.1 U3.3(~{INT}) ; port /INT
/PG: R36.1 U3.6(~{PG}) ; port /PG
ACN: C13.2 C16.1 R21.1 U3.29(ACN) ; port ACN
ACOV: C22.1 R31.1 R32.2 U3.35(ACOV) ; port ACOV
ACP: C13.1 C15.1 R20.1 U3.30(ACP) ; port ACP
ACUV: C19.1 R30.1 R31.2 U3.34(ACUV) ; port ACUV
BAT: C35.2 C36.1(+) J2.3 R19.2 R24.1 R33.2 R34.2 ; port BAT
BTST1: C20.2 D1.1(CATHODE) U3.26(BTST1) ; port BTST1
BTST2: C21.1 D2.1(CATHODE) U3.20(BTST2) ; port BTST2
FB: C24.2 R34.1 R35.2 U3.12(FB) ; port FB
FBG: R35.1 U3.11(FBG) ; port FBG
FSW_SYNC: R40.2 U3.36(FSW_SYNC) ; port FSW_SYNC
HIDRV1: R25.2 U3.27(HIDRV1) ; port HIDRV1
HIDRV2: R22.2 U3.19(HIDRV2) ; port HIDRV2
I2C_SCL: R43.1 ; off-sheet I2C_SCL
I2C_SDA: R42.1 ; off-sheet I2C_SDA
ICHG: R45.2 U3.9(ICHG) ; port ICHG
ILIM_HIZ: R44.2 U3.10(ILIM_HIZ) ; port ILIM_HIZ
LDO_3V3: R36.2 R37.2 R38.2 R39.2 ; off-sheet LDO_3V3
LODRV1: R28.1 U3.25(LODRV1) ; port LODRV1
LODRV2: R29.1 U3.21(LODRV2) ; port LODRV2
MODE: R41.2 U3.17(MODE) ; port MODE
P_OUT: C29.1(+) C30.2 C32.1 Q1.5(D) Q1.6(D) Q1.7(D) Q1.8(D) Q1.9(D) R19.1 R23.1 ; port P_OUT
PPHV: C25.1 C33.1(+) C34.1 R18.1 R20.2 R30.2 U3.32(VAC) U3.33(VAC) ; off-sheet PPHV
REGN: C23.1 C26.1 D1.2(ANODE) D2.2(ANODE) R26.2 U3.23(DRV_SUP) U3.24(REGN) ; port REGN
SRN: C14.2 C18.1 R24.2 U3.13(SRN) ; port SRN
SRP: C14.1 C17.1 R23.2 U3.14(SRP) ; port SRP
STAT1: R38.1 U3.4(STAT1) ; port STAT1
STAT2: R39.1 U3.5(STAT2) ; port STAT2
SW1: C20.1 L2.1 Q2.1(S) Q2.2(S) Q2.3(S) Q4.5(D) Q4.6(D) Q4.7(D) Q4.8(D) Q4.9(D) U3.28(SW1) ; port SW1
SW2: C21.2 L2.2 Q1.1(S) Q1.2(S) Q1.3(S) Q3.5(D) Q3.6(D) Q3.7(D) Q3.8(D) Q3.9(D) U3.18(SW2) ; port SW2
TS: J2.2 R26.1 R27.2 U3.8(TS) ; port TS
VSYS: C27.1(+) C28.2 C31.1 Q2.5(D) Q2.6(D) Q2.7(D) Q2.8(D) Q2.9(D) R18.2 R21.2 ; port VSYS
NetC24_1: C24.1 R33.1
NetQ1_4: Q1.4(G) R22.1
NetQ2_4: Q2.4(G) R25.1
NetQ3_4: Q3.4(G) R29.2
NetQ4_4: Q4.4(G) R28.2
NetR42_2: R42.2 U3.2(SDA)
NetR43_2: R43.2 U3.1(SCL)

Not connected (* = marked no-connect by the designer): U3 15(NC)* 16(NC)* 31(NC)*

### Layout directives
net class HV: ACN, ACP, ACUV, BTST1, HIDRV1, NetQ2_4, SW1, VSYS
net class HHV: BAT, BTST2, HIDRV2, NetQ1_4, P_OUT, SRN, SRP, SW2
net class LV: LODRV1, LODRV2, PGND

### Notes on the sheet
- From USB Port: 5-20V
- (near R18) 2m default, higher Resister for better regulation
- (near R19) 5m is fixed, do not change
- 4S-7S/16V-31.5V/900mA
- To BATTERY PACK
- (near L2) L: 2.2uH-15uH DCR: 1.75m-60m
- JEITA compliance
- UV-4.2v  OV-SET to 25
- Use Kelvin sense for ACP/ACN
- Use Kelvin sense for SRP/SRN
- (near C19) ACUV=1.1V
- (near R31) VAC_UV_DPM minimum setting is 4.2V
- SiSS50DN
- (near R27) add 10K resistor on Ts pin to emulate the normal temperarure operation if no external NTC resistor placed across it
- ACOV=1.2V
- (near R32) R52 for ACOV setting
- 7S BAT Selection Table
- VFB=1.536V
- VBAT
- 7S/31.5V
- 15K
- 12.7K
- R47(Rfblow)
- Default 3K
- EVM Set to 300KHz
- (near R35) 7S (31.5V)
- 4S/18V
- 6S/27V
- 5S/22.5V
- 23.2K
- 18.3K
- 1,FBG Pin internal to ground 12R resistor
  2, turn off feedback network to minimize feedback resistor loss when not working
- Set Charge current throuhg ICHG pin or Register, the lower will win
- (near R44) Set Input Current Limit throuhg ILIM_HIZ pin or Register, the lower will win
- ICHG=KICHG/RCHG=900mA
- ILIM=KLIM/RLIM=3A
- KICHG=50A*Kohm
- KLIM=50A*Kohm for 2m Input Current Sense
- KLIM=20A*Kohm for 5m Input Current Sense
- Text

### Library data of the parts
C13 C14 = CMP-0006944-4: CAP, CERM, 0.47 uF, 16 V, +/- 10%, X7R, 0603; Manufacturer: Kemet; TaMin_C: -55°C; Polarized: N; SizeAreaWB_mm2: 4.68; Value1: Unknown; U/M: EA; Value: 0.47uF; TaMax_C: 125°C; SizeZ_mm: 1; SizeX_mm: 1.6; SizeY_mm: 0.8; SizeArea_mm2: 1.28; AEC Category: Q200
C15-C19 C22 = CMP-0081011-1: CAP, CERM, 0.1 µF, 100 V,+/- 10%, X7R, AEC-Q200 Grade 1, 0603; Manufacturer: Taiyo Yuden; SizeAreaWB_mm2: 4.68; SizeArea_mm2: 1.28; AEC Qualified: Y; AEC Category: Q200; Value: 0.1uF; TaMax_C: 125°C; SizeZ_mm: 1; Polarized: N; TaMin_C: -55°C; SizeY_mm: 0.8; U/M: EA; SizeX_mm: 1.6; Cap_Case: 0603; ValueDisplayed: 0.1µF
C20 C21 = CMP-0006753-4: CAP, CERM, 0.1 uF, 25 V, +/- 10%, X7R, 0603; Manufacturer: AVX; TaMin_C: -55°C; ESR_ohm: 50m; Polarized: N; SizeAreaWB_mm2: 4.68; Value1: 0.05 ohm; U/M: EA; Value: 0.1uF; TaMax_C: 125°C; SizeZ_mm: 1; SizeX_mm: 1.6; SizeY_mm: 0.8; Cap_Case: 0603; SizeArea_mm2: 1.28; AEC Category: Q200
C23 C26 = CMP-0093626-1: Cap Ceramic 4.7uF 25V X7R 10% Pad SMD 0805 +125°C Automotive T/R; Manufacturer: TDK Corporation; SizeZ_mm: 1.45mm; TempCo: 15%; AEC Qualified: Yes; Value: 4.7µF; Tolerance_%: 0.1%; AEC Grade: Grade 1
C24 = CMP-0007130-4: CAP, CERM, 100 pF, 100 V, +/- 5%, C0G/NP0, AEC-Q200 Grade 1, 0603; Manufacturer: MuRata; TaMin_C: -55°C; Polarized: N; SizeAreaWB_mm2: 4.68; Value1: Unknown; U/M: EA; TaMax_C: 125°C; SizeZ_mm: 1; SizeX_mm: 1.6; SizeY_mm: 0.8; Cap_Case: 0603; SizeArea_mm2: 1.28; AEC Qualified: Y; AEC Category: Q200; Value: 100pF
C25 = CMP-0861070-1: CAP, CERM, 1 µF, 100 V,+/- 10%, X7R, AEC-Q200 Grade 1, 0805; Manufacturer: AVX; SizeZ_mm: 1.5; Polarized: N; TaMax_C: 125°C; TaMin_C: -55°C; Value: 1uF; AEC Qualified: Y; U/M: EA; AEC Grade: 1; Cap_Case: 0805; SizeX_mm: 2; SizeArea_mm2: 2.5; SizeAreaWB_mm2: 6.75; AEC Category: Q200; SizeY_mm: 1.25
C27 = CMP-0012588-1: CAP, Polymer Hybrid, 47 uF, 35 V, +/- 20%, 60 ohm, 6.3x5.8 SMD; Manufacturer: Panasonic; TaMin_C: -55°C; ESR_ohm: 60; Polarized: Y; SizeAreaWB_mm2: 79.98; Value1: 60 ohm; U/M: EA; Value: 47uF; TaMax_C: 105°C; SizeZ_mm: 6; SizeX_mm: 7.3; SizeY_mm: 6.6; SizeArea_mm2: 48.18; CompType: Capacitor; Cap_F: 47µF; IRMS_A: 1.3A; AEC Category: Q200
C28 C30 C34 C35 = CMP-0088943-1: 4.7µF ±10% 50V Ceramic Capacitor X7R 0805 (2012 Metric); Manufacturer: TDK; TempCo: 15%; AEC Qualified: No; ValueDisplayed: 4.7uF; SizeZ_mm: 1.5mm
C29 C36 = CMP-0011409-1: CAP, AL, 47 uF, 50 V, +/- 20%, SMD; Manufacturer: Nichicon; TaMin_C: -55°C; Polarized: Y; SizeAreaWB_mm2: 77.4; Value1: Unknown; U/M: EA; Value: 47uF; TaMax_C: 105°C; SizeZ_mm: 6.1; SizeX_mm: 7; SizeY_mm: 6.6; Cap_Case: 6.3x5.8mm; SizeArea_mm2: 46.2; CompType: Capacitor; AEC Qualified: N; Cap_F: 47µF; IRMS_A: 195mA; AEC Category: Q200
C31 C32 = CMP-0006861-3: CAP, CERM, 0.1 uF, 50 V, +/- 10%, X7R, 0603; Manufacturer: Kemet; TaMin_C: -55°C; Polarized: N; SizeAreaWB_mm2: 4.68; Value1: Unknown; U/M: EA; Value: 0.1uF; TaMax_C: 125°C; SizeZ_mm: 1; SizeX_mm: 1.6; SizeY_mm: 0.8; SizeArea_mm2: 1.28; AEC Category: Q200
C33 = CMP-0012262-1: CAP, Aluminum Polymer, 68 uF, 35 V, +/- 20%, 0.035 ohm, AEC-Q200 Grade 1, D6.3xL7.7mm SMD; Manufacturer: Panasonic; TaMin_C: -55°C; ESR_ohm: 35m; Polarized: Y; U/M: EA; Value: 68uF; TaMax_C: 125°C; Cap_Case: 6.3x7.7mm; CompType: Capacitor; Cap_F: 68µF; IRMS_A: 1.4A; AEC Grade: 1; AEC Category: Q200
D1 D2 = CMP-0093639-2: Diode Schottky 1A Surface Mount DO-219AB (SMF); Manufacturer: Vishay; Max Surge Forward Current: 30A; TJmax_C: 175°C; AEC Qualified: No; Cap_F: 95pF; AEC Category: Q101; Standoff Height: 0mm; SizeZ_mm: 1.08mm; Vr_V: 100V; Peak Reverse Current: 0.2uA
J2 = CMP-0055500-1: Terminal Block, 3x1, 2.54 mm, TH; Manufacturer: Phoenix Contact; CNHeader: FALSE; Green_Lifecycle: Not Set; Green_REACh: Incomplete; CT: TRUE
L2 = CMP-0098924-1: Cyntech, 8.2uH, 5.3A, 45mOhm; DC Resistance: 43mOhm; Match Code: WE-LHMI; Performance Rated Current: 4.35A; Saturation Current: 12.2A; Self Resonant Frequency: 15MHz
Q1-Q4 = CMP-0000866-2: MOSFET, N-CH, 45 V, 4mR, PowerPAK 1212; Alternate Manufacturer: None; Manufacturer: Vishay-Siliconix; SizeZ_mm: 1.04; ChType: N; Value2: 13 nC; Value1: 0.07; VdsMax_V: 60V; SizeX_mm: 3.3; SizeAreaWB_mm2: 18.49; Vgs_V: 20V; QgTyp_nC: 13; Value: 45V; Rdson45_ohm: 72m; SizeArea_mm2: 10.89; AEC Category: Q101; IdsMax_A: 6A; U/M: EA
R18 R19 = CMP-0021984-1: RES, 0.005, 1%, 0.5 W, 0805; Manufacturer: Vishay-Dale; Power_W: 500mW; TempCo: 110 ppm/C; Value_Code: 5L000; U/M: EA; Value: 0.005; EIA_Code: E96; Res_ohm: 5m; SizeX_mm: 2.03; SizeY_mm: 1.27; SizeZ_mm: 0.584; Value2: 0.5W; SizeArea_mm2: 2.5781; AEC Qualified: N; AEC Category: Q200
R20 R21 R23 R24 = CMP-0093685-1: RES Thick Film, 10Ω, 1%, 0.1W, 100ppm/°C, 0603; Manufacturer: Vishay; Approved Alternate Part Number: 541-1.00HHCT-ND; Power_W: 100mW; Voltage: 75V; SizeZ_mm: 0.5mm; AEC Grade: Grade 0; AEC Qualified: Yes
R22 R25 R28 R29 = CMP-0093629-1: Thick Film Resistors - SMD 1/10watt ZEROohm Jumper; Manufacturer: Vishay; AEC Grade: Grade 0; TempCo: 100ppm/°C; Power: 250mW; Res_ohm: 1.5; Power_W: 330mW; AEC Qualified: Yes; VDC_V: 75V; SizeZ_mm: 0.55mm; Tolerance_%: 1%
R26 = CMP-0023199-5: RES, 5.23 k, 1%, 0.1 W, 0603; Manufacturer: Yageo; Power_W: 100mW; TempCo: 100 ppm/C; Value_Code: 5k23; Value: 5.23k; EIA_Code: E96; SizeX_mm: 1.6; SizeY_mm: 0.8; SizeZ_mm: 1; Value2: 0.1W; SizeArea_mm2: 1.28; AEC Qualified: N; VDC_V: 75V; AEC Category: Q200; SizeAreaWB_mm2: 4.68
R27 = CMP-0023018-5: RES, 30.1 k, 1%, 0.1 W, 0603; Manufacturer: Yageo; Power_W: 100mW; TempCo: 100 ppm/C; Value_Code: 30k1; Value: 30.1k; EIA_Code: E96; SizeX_mm: 1.6; SizeY_mm: 0.8; SizeZ_mm: 1; Value2: 0.1W; SizeArea_mm2: 1.28; AEC Qualified: N; VDC_V: 75V; AEC Category: Q200; SizeAreaWB_mm2: 4.68
R30 = CMP-0021522-3: Thick Film Resistors - SMD 1/8Watt 1Mohms 1% Commercial Use; Manufacturer: Vishay / Dale; Power_W: 125mW; TempCo: 100 ppm/C; Value_Code: 1M00; Value: 1.00Meg; EIA_Code: E96; Res_ohm: 1M; SizeX_mm: 2; SizeY_mm: 1.25; SizeZ_mm: 1.45; Value2: 0.125W; SizeArea_mm2: 2.5; AEC Qualified: Y; AEC Category: Q200; AEC Grade: 0; SizeAreaWB_mm2: 6.75
R31 = CMP-0025195-3: RES, 383 k, 0.5%, 0.1 W, 0603; Manufacturer: Yageo America; Power_W: 100mW; TempCo: 50 ppm/C; U/M: EA; Value: 383k; EIA_Code: E192; SizeX_mm: 1.6; SizeY_mm: 0.8; SizeZ_mm: 1; Value2: 0.1W; SizeArea_mm2: 1.28; VDC_V: 75V; AEC Category: Q200
R32 = CMP-0025509-3: RES, 69.8 k, 0.5%, 0.1 W, 0603; Manufacturer: Yageo America; Power_W: 100mW; TempCo: 50 ppm/C; Value_Code: 69k8; U/M: EA; Value: 69.8k; EIA_Code: E192; SizeX_mm: 1.6; SizeY_mm: 0.8; SizeZ_mm: 1; Value2: 0.1W; SizeArea_mm2: 1.28; VDC_V: 75V; AEC Category: Q200
R33 = CMP-0025744-3: RES, 1.1, 5%, 0.1 W, 0603; Manufacturer: Vishay-Dale; Power_W: 100mW; TempCo: 200 ppm/C; Value_Code: 1R10; U/M: EA; Value: 1.1; EIA_Code: E24; SizeX_mm: 1.6; SizeY_mm: 0.8; SizeZ_mm: 1; Value2: 0.1W; SizeArea_mm2: 1.28; VDC_V: 75V; AEC Category: Q200
R34 = CMP-0018933-2: Thick Film Resistors - SMD 0805 Anti-Surge Res. 0.1%, 249Kohm; Manufacturer: Panasonic; Power_W: 125mW; TempCo: 25 ppm/C; U/M: EA; Value: 249k; EIA_Code: E192; SizeX_mm: 2; SizeY_mm: 1.25; SizeZ_mm: 1.45; Value2: 0.125W; SizeArea_mm2: 2.5; VDC_V: 100V; AEC Category: Q200
R35 = CMP-0023708-2: RES, 12.7 k, 0.1%, 0.1 W, 0603; Manufacturer: Yageo America; Power_W: 100mW; TempCo: 25 ppm/C; Value_Code: 12k7; U/M: EA; Value: 12.7k; EIA_Code: E192; SizeX_mm: 1.6; SizeY_mm: 0.8; SizeZ_mm: 1; Value2: 0.1W; SizeArea_mm2: 1.28; VDC_V: 75V; AEC Category: Q200
R36-R39 = CMP-0078781-1: RES, 10.5 k, 1%, 0.063 W, 0402; Manufacturer: Yageo America; Value_Code: 10k5; SizeArea_mm2: 0.5; AEC Qualified: N; AEC Category: Q200; Value: 10.5k; SizeZ_mm: 0.6; EIA_Code: E96; TempCo: 100 ppm/C; Power_W: 63mW; VDC_V: 50V; Value2: 0.063W; SizeX_mm: 1
R40 = CMP-0022735-5: RES, 100 k, 1%, 0.1 W, 0603; Manufacturer: Yageo; Power_W: 100mW; TempCo: 100 ppm/C; Value: 100k; EIA_Code: E96; SizeX_mm: 1.6; SizeY_mm: 0.8; SizeZ_mm: 1; Value2: 0.1W; SizeArea_mm2: 1.28; AEC Qualified: N; VDC_V: 75V; AEC Category: Q200; SizeAreaWB_mm2: 4.68
R41 = CMP-0022371-2: RES, 3.01 k, 1%, 0.1 W, 0603; Manufacturer: Vishay-Dale; Power_W: 100mW; TempCo: 100 ppm/C; Value_Code: 3k01; U/M: EA; Value: 3.01k; EIA_Code: E96; SizeX_mm: 1.6; SizeY_mm: 0.8; SizeZ_mm: 1; Value2: 0.1W; SizeArea_mm2: 1.28; VDC_V: 75V; AEC Category: Q200
R42 R43 = CMP-0026898-1: RES, 2.2, 5%, 0.063 W, 0402; Manufacturer: Vishay-Dale; Power_W: 63mW; TempCo: 200 ppm/C; Value_Code: 2R20; U/M: EA; Value: 2.2; EIA_Code: E24; SizeX_mm: 1; SizeY_mm: 0.5; SizeZ_mm: 0.6; Value2: 0.063W; VDC_V: 50V; AEC Category: Q200
R44 = CMP-0024438-1: RES, 6.65 k, 0.1%, 0.1 W, 0603; Manufacturer: Yageo America; Power_W: 100mW; TempCo: 25 ppm/C; Value_Code: 6k65; U/M: EA; Value: 6.65k; EIA_Code: E192; SizeX_mm: 1.6; SizeY_mm: 0.8; SizeZ_mm: 1; Value2: 0.1W; SizeArea_mm2: 1.28; VDC_V: 75V; AEC Category: Q200
R45 = CMP-0023575-1: RES, 56.2 k, 0.1%, 0.1 W, 0603; Manufacturer: Susumu Co Ltd; Power_W: 100mW; TempCo: 25 ppm/C; Value_Code: 56k2; U/M: EA; Value: 56.2k; EIA_Code: E192; SizeX_mm: 1.6; SizeY_mm: 0.8; SizeZ_mm: 1; Value2: 0.1W; SizeArea_mm2: 1.28; VDC_V: 75V; AEC Category: Q200
U3 = CMP-0093460-1: Manufacturer: Texas Instruments; Alternate Manufacturer: None; AEC Qualified: No; Standoff Height: 0mm; SizeZ_mm: 1mm

## Sheet Hardware.SchDoc
size A2; Date: Not shown in title block; ApprovedBy: Not shown in title block; CheckedBy: Not shown in title block; Author: Not shown in title block; CompanyName: Not shown in title block; Engineer: Not shown in title block; Organization: Not shown in title block; Address1: Not shown in title block; Address2: Not shown in title block; Address3: Not shown in title block; Address4: Not shown in title block; DocumentNumber: 1; Revision: Use project parameter SCH_Rev; SheetNumber: 4; SheetTotal: 4; PageSetup: Record=PageOptions¦CenterHorizontal=True¦CenterVertical=True¦PrintScale=1.00¦XCorrection=1.00¦YCorrection=1.00¦PrintKind=0¦BorderSize=5000000¦LeftOffset=0¦BottomOffset=0¦Orientation=2¦PaperLength=1000¦PaperWidth=1000¦Scale=100¦PaperSource=15¦PrintQuality=600¦MediaType=1¦DitherType=10¦PaperKind=Letter¦PrintScaleMode=1
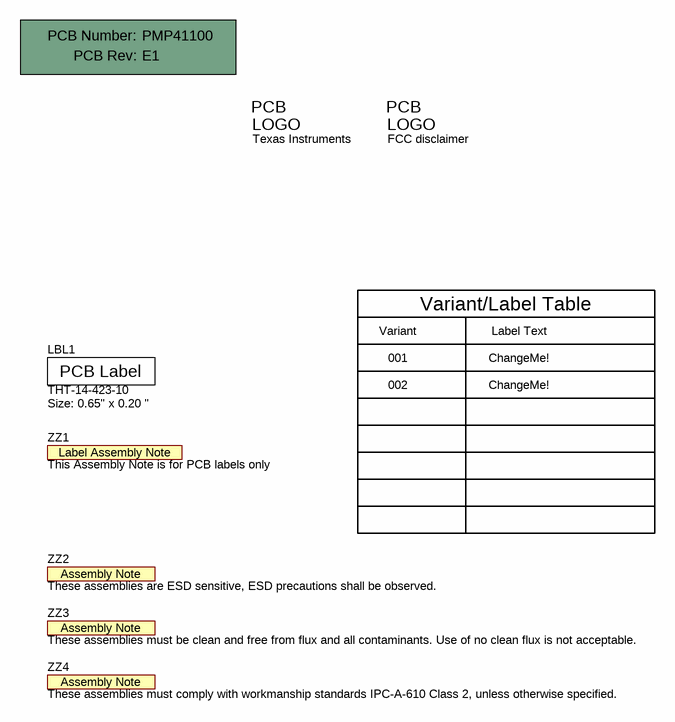
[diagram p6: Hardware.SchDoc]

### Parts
!PCB1  Printed Circuit Board  (value not drawn)  (mechanical)
LBL1  THT-14-423-10  Note: Size: 0.65" x 0.20 "  [Label_650x200]
Logo1  Texas Instruments  [TI_Stacked_Overlay_Small]  (no BOM)
Logo2  FCC disclaimer  [FCC_disclaimer]  (no BOM)
ZZ1  This Assembly Note is for PCB labels only  [AssemblyNoteLabel]  (no BOM)
ZZ2  These assemblies are ESD sensitive, ESD precautions shall be observed.  [AssemblyNote]  (no BOM)
ZZ3  These assemblies must be clean and free from flux and all contaminants. Use of no clean flux is not acceptable.  [AssemblyNote]  (no BOM)
ZZ4  These assemblies must comply with workmanship standards IPC-A-610 Class 2, unless otherwise specified.  [AssemblyNote]  (no BOM)

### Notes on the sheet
- Variant
- Variant/Label Table
- Label Text
- 001
- 002
- ChangeMe!

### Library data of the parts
!PCB1 = CMP-0003618-2: Manufacturer: Any; PartNumber: PMP41100
LBL1 = CMP-0003625-1: Thermal Transfer Printable Labels, 0.650" W x 0.200" H - 10,000 per roll; Manufacturer: Brady; CompType: Label
Logo1 = CMP-0074838-1: Texas Instrument Corporate Signature; SymbolCreator: a0412235; Lib Reference: TI_Logo; Library Reference: Logo
Logo2 = CMP-0074847-1: FCC_disclaimer; Library Reference: Logo
ZZ1 = CMP-0003616-3
ZZ2 = CMP-0077236-1
ZZ3 = CMP-0077237-1
ZZ4 = CMP-0077238-1

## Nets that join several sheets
PGND: PD Controller (42 pins), Charger BQ25756 (35 pins)
I2C_SCL: PD Controller (R10.2 U2.9), Charger BQ25756 (R43.1)
I2C_SDA: PD Controller (R11.2 U2.8), Charger BQ25756 (R42.1)
LDO_3V3: PD Controller (9 pins), Charger BQ25756 (R36.2 R37.2 R38.2 R39.2)

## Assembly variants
001: not fitted R10 R11 R42 R43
